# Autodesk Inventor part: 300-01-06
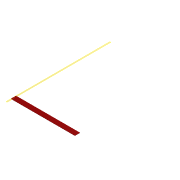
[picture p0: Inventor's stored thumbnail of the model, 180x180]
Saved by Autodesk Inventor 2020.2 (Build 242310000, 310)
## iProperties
Created: 2014-11
Part Number: 300-01-06
Material: Stal
Document SubType Name: Modeling
Designer: F.Stasiak
Density: 7.85 g/cm^3
Appearance: Czerwona
Catalog Web Link: www.expertbooks.pl
Manager: www.cadconsulting.pl
Company: Fabian Stasiak CAD Consulting
Author: F.Stasiak
Subject: Zbiór ćwiczeń. Autodesk Inventor 2020. Kurs Professional
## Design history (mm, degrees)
node "Płaszczyzna konstrukcyjna1"
sketch "Szkic1"
  geometry: L1 (0, 0)-(815, 0); L2 (815, 0)-(815, 65); L3 (815, 65)-(0, 65); L4 (0, 65)-(0, 0)
  constraints: 8 end point, 2 parallel, 1 horizontal, 1 perpendicular
  dimensions: "d0" = 815 distance of L3.end L2.end; "d1" = 65 distance of L1.end L2.end
extrude "Wyciągnięcie proste1" new body sketch "Szkic1" distance "d2" = 3; taper "d3" = 0 deg
node "Bryła1"
